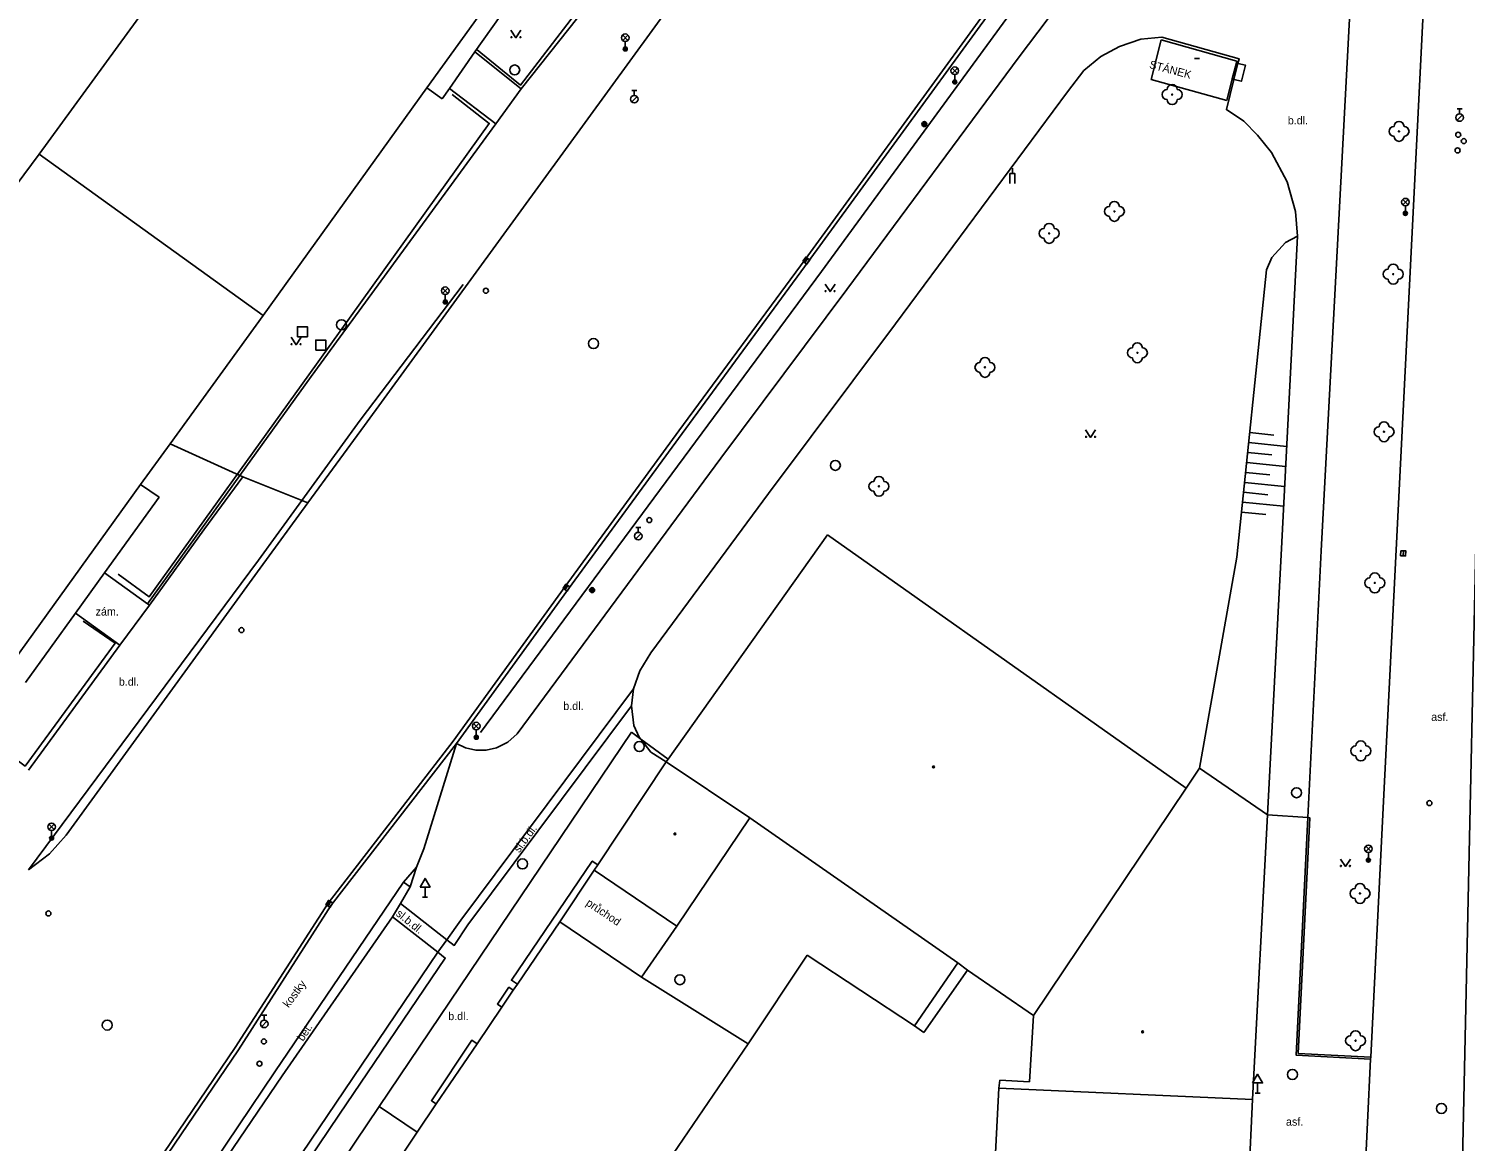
# Model space of a CAD drawing. Extents: x -599770 to -598493, y -1162076 to -1159209.
# Drawn here: x -599131.7 to -599059.8, y -1159691.3 to -1159635.7 of the extents above; entities that cross this region are included whole.
import ezdxf

# ---------------------------------------------------------------- set-up
doc = ezdxf.new("R2010")
doc.units = 0
doc.layers.add('Podklad', color=7, linetype='Continuous')

msp = doc.modelspace()

# ---------------------------------------------------------------- linework, layer by layer
at = {"layer": 'Podklad'}
for p, q in [((-599101.962, -1159636.26), (-599101.697, -1159635.995)), ((-599101.962, -1159635.995), (-599101.697, -1159636.26)), ((-599101.83, -1159636.315), (-599101.83, -1159636.69)), ((-599073.37, -1159637.16), (-599073.12, -1159637.16)), ((-599085.492, -1159637.91), (-599085.227, -1159637.645)), ((-599085.492, -1159637.645), (-599085.227, -1159637.91)), ((-599085.36, -1159637.965), (-599085.36, -1159638.34)), ((-599101.509, -1159639.336), (-599101.244, -1159639.071)), ((-599101.505, -1159638.762), (-599101.255, -1159638.762)), ((-599101.38, -1159639.012), (-599101.38, -1159638.762)), ((-599060.249, -1159640.256), (-599059.984, -1159639.991)), ((-599060.245, -1159639.683), (-599059.995, -1159639.683)), ((-599060.12, -1159639.933), (-599060.12, -1159639.683)), ((-599082.48, -1159642.92), (-599082.48, -1159642.655)), ((-599062.962, -1159644.48), (-599062.697, -1159644.215)), ((-599062.962, -1159644.215), (-599062.697, -1159644.48)), ((-599062.83, -1159644.535), (-599062.83, -1159644.91)), ((-599092.853, -1159647.372), (-599092.707, -1159647.168)), ((-599110.962, -1159648.91), (-599110.697, -1159648.645)), ((-599110.962, -1159648.645), (-599110.697, -1159648.91)), ((-599110.83, -1159648.965), (-599110.83, -1159649.34)), ((-599101.305, -1159660.613), (-599101.055, -1159660.613)), ((-599101.18, -1159660.863), (-599101.18, -1159660.613)), ((-599101.309, -1159661.186), (-599101.044, -1159660.921)), ((-599062.933, -1159661.785), (-599062.947, -1159662.035)), ((-599104.841, -1159663.723), (-599104.699, -1159663.517)), ((-599109.413, -1159670.68), (-599109.148, -1159670.415)), ((-599109.413, -1159670.415), (-599109.148, -1159670.68)), ((-599109.28, -1159670.735), (-599109.28, -1159671.11)), ((-599130.643, -1159675.72), (-599130.378, -1159675.455)), ((-599130.643, -1159675.455), (-599130.378, -1159675.72)), ((-599130.51, -1159675.775), (-599130.51, -1159676.15)), ((-599064.812, -1159676.82), (-599064.547, -1159676.555)), ((-599064.812, -1159676.555), (-599064.547, -1159676.82)), ((-599064.68, -1159676.875), (-599064.68, -1159677.25)), ((-599111.84, -1159678.601), (-599111.84, -1159679.11)), ((-599116.692, -1159679.548), (-599116.568, -1159679.332)), ((-599111.965, -1159679.11), (-599111.715, -1159679.11)), ((-599120.005, -1159685.003), (-599119.755, -1159685.003)), ((-599119.88, -1159685.253), (-599119.88, -1159685.003)), ((-599120.009, -1159685.576), (-599119.744, -1159685.311)), ((-599070.22, -1159688.391), (-599070.22, -1159688.9)), ((-599070.345, -1159688.9), (-599070.095, -1159688.9))]:
    msp.add_line(p, q, dxfattribs=at)
for points in [[(-599081.54, -1159609.68), (-599084.49, -1159613.78), (-599087.085, -1159617.344), (-599114.87, -1159655.51)], [(-599070, -1159616.2), (-599070.21, -1159616.14), (-599079.64, -1159629.06), (-599092.84, -1159647.22), (-599099.15, -1159655.79), (-599104.83, -1159663.57), (-599110.43, -1159671.3), (-599116.69, -1159679.4), (-599121.33, -1159686.62), (-599127.73, -1159696.07), (-599130.7, -1159701.68), (-599133.59, -1159706.51), (-599136.75, -1159712.55), (-599137.64, -1159714.18), (-599138.29, -1159715.58), (-599145.74, -1159730.68), (-599147.39, -1159734.16)], [(-599104.67, -1159663.69), (-599098.99, -1159655.91), (-599092.68, -1159647.34), (-599079.48, -1159629.18), (-599070, -1159616.2)], [(-599109.07, -1159670.87), (-599092.02, -1159647.81), (-599078.8, -1159629.73), (-599071.94, -1159620.17), (-599070.03, -1159618.39), (-599068.94, -1159616.98)], [(-599068.94, -1159616.98), (-599068.84, -1159617.12), (-599068.63, -1159617.54), (-599068.53, -1159617.94), (-599068.5, -1159618.27), (-599068.57, -1159618.74), (-599077.37, -1159630.76), (-599082.14, -1159637.08), (-599090.75, -1159648.72)], [(-599061.78, -1159618.02), (-599062.25, -1159618.13), (-599062.76, -1159618.36), (-599063.23, -1159618.64), (-599063.66, -1159618.96), (-599064.04, -1159619.33), (-599064.4, -1159619.8), (-599064.68, -1159620.26), (-599064.86, -1159620.72), (-599066.21, -1159646.17), (-599067.04, -1159661.78), (-599067.71, -1159675.12)], [(-599061.09, -1159617.92), (-599062.51, -1159646.18), (-599063.97, -1159675.3), (-599064.56, -1159687.1)], [(-599131.14, -1159641.95), (-599118.52, -1159624.64)], [(-599064.99, -1159695.953), (-599060.021, -1159694.564), (-599058.503, -1159624.689)], [(-599107.41, -1159632.6), (-599111.75, -1159638.64), (-599119.94, -1159650.02)], [(-599109.36, -1159636.83), (-599106.73, -1159633.13)], [(-599104.37, -1159634.98), (-599107.07, -1159638.5), (-599109.24, -1159636.73)], [(-599107.03, -1159638.69), (-599104.2, -1159635.11)], [(-599107.55, -1159635.755), (-599107.3, -1159636.13), (-599107.05, -1159635.755)], [(-599079.73, -1159638.83), (-599078.91, -1159637.77), (-599078.06, -1159637.06), (-599077.12, -1159636.56), (-599076.05, -1159636.2), (-599075, -1159636.1), (-599071.14, -1159637.18), (-599071.2, -1159637.41)], [(-599075.54, -1159638.21), (-599075.04, -1159636.24)], [(-599075.04, -1159636.24), (-599071.26, -1159637.3)], [(-599110.98, -1159639.19), (-599110.62, -1159638.67), (-599109.36, -1159636.83)], [(-599107.03, -1159638.69), (-599109.36, -1159636.83)], [(-599071.28, -1159637.38), (-599071.49, -1159638.19)], [(-599071.2, -1159637.41), (-599070.82, -1159637.5), (-599071.03, -1159638.3), (-599071.4, -1159638.21)], [(-599071.4, -1159638.21), (-599071.2, -1159637.41)], [(-599071.26, -1159637.3), (-599071.28, -1159637.38)], [(-599071.2, -1159637.41), (-599071.28, -1159637.38)], [(-599071.76, -1159639.27), (-599075.54, -1159638.21)], [(-599071.4, -1159638.21), (-599071.78, -1159639.72), (-599070.9, -1159640.3), (-599070.22, -1159641), (-599069.52, -1159641.87), (-599068.74, -1159643.33), (-599068.32, -1159644.81), (-599068.22, -1159646.05)], [(-599071.49, -1159638.19), (-599071.76, -1159639.27)], [(-599071.4, -1159638.21), (-599071.49, -1159638.19)], [(-599110.48, -1159638.97), (-599108.63, -1159640.41), (-599117.65, -1159652.99), (-599125.63, -1159664.08), (-599127.19, -1159662.96)], [(-599110.98, -1159639.19), (-599111.75, -1159638.64)], [(-599110.62, -1159638.67), (-599108.3, -1159640.43)], [(-599108.3, -1159640.43), (-599107.03, -1159638.69)], [(-599100.55, -1159666.88), (-599094.67, -1159658.92), (-599088.33, -1159650.43), (-599079.73, -1159638.83)], [(-599121.1, -1159658.02), (-599117.53, -1159653.07), (-599108.3, -1159640.43)], [(-599139.39, -1159653.05), (-599131.14, -1159641.95)], [(-599119.94, -1159650.02), (-599131.14, -1159641.95)], [(-599082.605, -1159643.42), (-599082.605, -1159642.92), (-599082.355, -1159642.92), (-599082.355, -1159643.42)], [(-599073.12, -1159672.65), (-599071.25, -1159662.1), (-599069.77, -1159647.73), (-599069.51, -1159647.12), (-599068.83, -1159646.37), (-599068.22, -1159646.05)], [(-599068.22, -1159646.05), (-599069.03, -1159661.67), (-599069.72, -1159674.98)], [(-599109.93, -1159648.46), (-599115.08, -1159655.25), (-599120.16, -1159662.25), (-599131.66, -1159677.74)], [(-599091.84, -1159648.445), (-599091.59, -1159648.82), (-599091.34, -1159648.445)], [(-599090.75, -1159648.72), (-599097.06, -1159657.15), (-599107.24, -1159670.93), (-599107.7, -1159671.35), (-599108.27, -1159671.64), (-599108.78, -1159671.75), (-599109.3, -1159671.76), (-599109.82, -1159671.63), (-599110.27, -1159671.42)], [(-599119.94, -1159650.02), (-599124.59, -1159656.44), (-599126.06, -1159658.47)], [(-599118.54, -1159651.105), (-599118.29, -1159651.48), (-599118.04, -1159651.105)], [(-599114.87, -1159655.51), (-599117.7, -1159659.38), (-599120.09, -1159662.66), (-599129.78, -1159676)], [(-599078.82, -1159655.735), (-599078.57, -1159656.11), (-599078.32, -1159655.735)], [(-599120.949, -1159658.09), (-599120.986, -1159658.076), (-599121.1, -1159658.02), (-599124.59, -1159656.44)], [(-599068.77, -1159656.57), (-599070.66, -1159656.37)], [(-599069.4, -1159656), (-599070.61, -1159655.87)], [(-599069.51, -1159656.99), (-599070.71, -1159656.87)], [(-599069.61, -1159657.98), (-599070.81, -1159657.86)], [(-599068.82, -1159657.57), (-599070.76, -1159657.36)], [(-599126.06, -1159658.47), (-599132.74, -1159667.73)], [(-599126.06, -1159658.47), (-599125.14, -1159659.11)], [(-599125.72, -1159664.43), (-599121.1, -1159658.02)], [(-599125.62, -1159664.5), (-599122.9, -1159660.73), (-599120.95, -1159658.09)], [(-599117.7, -1159659.38), (-599120.949, -1159658.09)], [(-599068.87, -1159658.56), (-599070.86, -1159658.36)], [(-599125.14, -1159659.11), (-599127.86, -1159662.88)], [(-599068.92, -1159659.56), (-599070.97, -1159659.35)], [(-599069.71, -1159658.98), (-599070.92, -1159658.86)], [(-599069.81, -1159659.97), (-599071.02, -1159659.85)], [(-599099.68, -1159672.2), (-599091.72, -1159660.98)], [(-599091.72, -1159660.98), (-599073.79, -1159673.65)], [(-599127.86, -1159662.88), (-599129.32, -1159664.9)], [(-599127.86, -1159662.88), (-599125.72, -1159664.43), (-599125.62, -1159664.5)], [(-599110.27, -1159671.42), (-599104.67, -1159663.69)], [(-599129.32, -1159664.9), (-599131.82, -1159668.37)], [(-599127.1, -1159666.5), (-599129.32, -1159664.9)], [(-599127.1, -1159666.5), (-599125.62, -1159664.5)], [(-599133.79, -1159671.11), (-599131.84, -1159672.55), (-599127.34, -1159666.41), (-599128.93, -1159665.3)], [(-599131.66, -1159672.76), (-599127.1, -1159666.5)], [(-599101.42, -1159668.69), (-599101.11, -1159667.78), (-599100.55, -1159666.88)], [(-599101.42, -1159668.69), (-599110.06, -1159680.25), (-599110.75, -1159681.23)], [(-599101.52, -1159669.53), (-599101.42, -1159668.69)], [(-599110.75, -1159681.23), (-599110.38, -1159681.52), (-599109.71, -1159680.49), (-599101.52, -1159669.53)], [(-599101.05, -1159671.2), (-599101.13, -1159671.1), (-599101.4, -1159670.52), (-599101.52, -1159669.53)], [(-599101.52, -1159670.86), (-599114.13, -1159689.57)], [(-599101.05, -1159671.2), (-599101.52, -1159670.86)], [(-599110.27, -1159671.42), (-599116.53, -1159679.51), (-599121.16, -1159686.73), (-599127.56, -1159696.17), (-599130.53, -1159701.78)], [(-599112.27, -1159677.6), (-599112.07, -1159677.11), (-599111.91, -1159676.69), (-599110.27, -1159671.42)], [(-599099.78, -1159672.34), (-599100.55, -1159671.86), (-599101.05, -1159671.2)], [(-599099.68, -1159672.2), (-599101.05, -1159671.2)], [(-599103.21, -1159677.49), (-599099.78, -1159672.34)], [(-599099.78, -1159672.34), (-599099.68, -1159672.2)], [(-599095.61, -1159675.14), (-599099.78, -1159672.34)], [(-599073.79, -1159673.65), (-599073.12, -1159672.65)], [(-599073.12, -1159672.65), (-599069.72, -1159674.98)], [(-599073.79, -1159673.65), (-599081.43, -1159685.02)], [(-599095.61, -1159675.14), (-599099.25, -1159680.56)], [(-599085.21, -1159682.39), (-599095.61, -1159675.14)], [(-599069.72, -1159674.98), (-599070.47, -1159689.22)], [(-599067.71, -1159675.12), (-599069.72, -1159674.98)], [(-599067.71, -1159675.12), (-599068.29, -1159687.01), (-599064.57, -1159687.2)], [(-599067.71, -1159675.12), (-599067.61, -1159675.13), (-599068.19, -1159686.92), (-599064.56, -1159687.1)], [(-599129.78, -1159676), (-599130.61, -1159676.93), (-599131.66, -1159677.74)], [(-599107.22, -1159683.46), (-599107.52, -1159683.26), (-599103.48, -1159677.3), (-599103.21, -1159677.49)], [(-599066.08, -1159677.195), (-599065.83, -1159677.57), (-599065.58, -1159677.195)], [(-599112.92, -1159678.36), (-599112.27, -1159677.6)], [(-599112.59, -1159678.59), (-599112.27, -1159677.6)], [(-599105.1, -1159680.33), (-599103.39, -1159677.76)], [(-599103.39, -1159677.76), (-599103.21, -1159677.49)], [(-599099.25, -1159680.56), (-599103.39, -1159677.76)], [(-599112.92, -1159678.36), (-599119.35, -1159687.83), (-599124.8, -1159695.93)], [(-599113.07, -1159679.42), (-599112.59, -1159678.59)], [(-599112.59, -1159678.59), (-599112.92, -1159678.36)], [(-599113.47, -1159680.09), (-599113.07, -1159679.42)], [(-599113.07, -1159679.42), (-599110.75, -1159681.23)], [(-599124.49, -1159696.14), (-599118.98, -1159688.03), (-599113.47, -1159680.09)], [(-599113.47, -1159680.09), (-599111.2, -1159681.86)], [(-599107.22, -1159683.46), (-599105.1, -1159680.33)], [(-599105.1, -1159680.33), (-599101.02, -1159683.1)], [(-599099.25, -1159680.56), (-599101.02, -1159683.1)], [(-599110.75, -1159681.23), (-599111.2, -1159681.86)], [(-599111.2, -1159681.86), (-599121.81, -1159697.57), (-599126.73, -1159704.94), (-599128.45, -1159707.76), (-599130.07, -1159710.85), (-599131.65, -1159713.97)], [(-599111.2, -1159681.86), (-599110.83, -1159682.15), (-599116.12, -1159689.95), (-599121.42, -1159697.83), (-599122.55, -1159699.48)], [(-599095.69, -1159686.44), (-599092.73, -1159682.01)], [(-599092.73, -1159682.01), (-599087.37, -1159685.53)], [(-599085.21, -1159682.39), (-599087.37, -1159685.53)], [(-599084.73, -1159682.75), (-599085.21, -1159682.39)], [(-599101.02, -1159683.1), (-599095.69, -1159686.44)], [(-599086.9, -1159685.87), (-599084.73, -1159682.75)], [(-599081.43, -1159685.02), (-599084.73, -1159682.75)], [(-599108, -1159684.6), (-599108.22, -1159684.45), (-599107.65, -1159683.61), (-599107.43, -1159683.76)], [(-599108, -1159684.6), (-599107.43, -1159683.76)], [(-599107.43, -1159683.76), (-599107.22, -1159683.46)], [(-599109.24, -1159686.43), (-599108, -1159684.6)], [(-599081.63, -1159688.33), (-599081.43, -1159685.02)], [(-599087.37, -1159685.53), (-599086.9, -1159685.87)], [(-599111.28, -1159689.44), (-599111.52, -1159689.28), (-599109.5, -1159686.25), (-599109.24, -1159686.43)], [(-599111.28, -1159689.44), (-599109.24, -1159686.43)], [(-599095.69, -1159686.44), (-599099.69, -1159692.3)], [(-599064.57, -1159687.2), (-599064.88, -1159693.54)], [(-599064.56, -1159687.1), (-599064.57, -1159687.2)], [(-599083.35, -1159692.54), (-599083.16, -1159688.66)], [(-599083.16, -1159688.66), (-599083.1, -1159688.25)], [(-599070.47, -1159689.22), (-599083.16, -1159688.66)], [(-599083.1, -1159688.25), (-599081.63, -1159688.33)], [(-599114.13, -1159689.57), (-599121.33, -1159700.27)], [(-599112.24, -1159690.86), (-599114.13, -1159689.57)], [(-599112.24, -1159690.86), (-599111.28, -1159689.44)], [(-599070.47, -1159689.22), (-599070.65, -1159693.16)], [(-599117.36, -1159698.54), (-599112.24, -1159690.86)]]:
    msp.add_lwpolyline(points, dxfattribs=at)
for points in [[(-599092.751, -1159647.444), (-599092.606, -1159647.241), (-599092.809, -1159647.096), (-599092.954, -1159647.299)], [(-599118.22, -1159651.08), (-599117.72, -1159651.08), (-599117.72, -1159650.58), (-599118.22, -1159650.58)], [(-599117.31, -1159651.75), (-599116.81, -1159651.75), (-599116.81, -1159651.25), (-599117.31, -1159651.25)], [(-599063.058, -1159661.778), (-599063.072, -1159662.028), (-599062.822, -1159662.042), (-599062.808, -1159661.792)], [(-599104.739, -1159663.794), (-599104.596, -1159663.589), (-599104.801, -1159663.446), (-599104.944, -1159663.651)], [(-599112.09, -1159678.601), (-599111.59, -1159678.601), (-599111.84, -1159678.168)], [(-599116.584, -1159679.611), (-599116.459, -1159679.394), (-599116.676, -1159679.269), (-599116.801, -1159679.486)], [(-599070.47, -1159688.391), (-599069.97, -1159688.391), (-599070.22, -1159687.958)]]:
    msp.add_lwpolyline(points, close=True, dxfattribs=at)
for centre, radius in [((-599107.525, -1159636.105), 0.025), ((-599107.075, -1159636.105), 0.025), ((-599101.83, -1159636.128), 0.188), ((-599101.83, -1159636.69), 0.1), ((-599101.83, -1159636.69), 0.0723), ((-599101.83, -1159636.69), 0.0438), ((-599107.36, -1159637.74), 0.25), ((-599085.36, -1159637.777), 0.188), ((-599085.36, -1159638.34), 0.1), ((-599085.36, -1159638.34), 0.0723), ((-599085.36, -1159638.34), 0.0438), ((-599101.38, -1159639.2), 0.188), ((-599074.49, -1159638.97), 0.025), ((-599060.12, -1159640.12), 0.188), ((-599086.88, -1159640.45), 0.125), ((-599086.88, -1159640.45), 0.1), ((-599086.88, -1159640.45), 0.075), ((-599086.88, -1159640.45), 0.05), ((-599086.88, -1159640.45), 0.025), ((-599063.15, -1159640.81), 0.025), ((-599060.19, -1159640.98), 0.125), ((-599059.91, -1159641.3), 0.125), ((-599060.22, -1159641.76), 0.125), ((-599062.83, -1159644.347), 0.188), ((-599077.38, -1159644.81), 0.025), ((-599062.83, -1159644.91), 0.1), ((-599062.83, -1159644.91), 0.0723), ((-599062.83, -1159644.91), 0.0438), ((-599080.64, -1159645.91), 0.025), ((-599063.44, -1159647.95), 0.025), ((-599110.83, -1159648.777), 0.188), ((-599108.8, -1159648.78), 0.125), ((-599110.83, -1159649.34), 0.1), ((-599110.83, -1159649.34), 0.0723), ((-599110.83, -1159649.34), 0.0438), ((-599091.815, -1159648.795), 0.025), ((-599091.365, -1159648.795), 0.025), ((-599116.02, -1159650.48), 0.25), ((-599118.515, -1159651.455), 0.025), ((-599118.065, -1159651.455), 0.025), ((-599103.42, -1159651.42), 0.25), ((-599076.23, -1159651.88), 0.025), ((-599083.85, -1159652.61), 0.025), ((-599063.9, -1159655.83), 0.025), ((-599078.795, -1159656.085), 0.025), ((-599078.345, -1159656.085), 0.025), ((-599091.33, -1159657.51), 0.25), ((-599089.15, -1159658.56), 0.025), ((-599100.63, -1159660.25), 0.125), ((-599101.18, -1159661.05), 0.188), ((-599103.49, -1159663.75), 0.125), ((-599103.49, -1159663.75), 0.1), ((-599103.49, -1159663.75), 0.075), ((-599103.49, -1159663.75), 0.05), ((-599103.49, -1159663.75), 0.025), ((-599064.36, -1159663.39), 0.025), ((-599121.02, -1159665.75), 0.125), ((-599109.28, -1159670.547), 0.188), ((-599109.28, -1159671.11), 0.1), ((-599109.28, -1159671.11), 0.0723), ((-599109.28, -1159671.11), 0.0438), ((-599101.13, -1159671.57), 0.25), ((-599065.06, -1159671.79), 0.025), ((-599086.42, -1159672.59), 0.045), ((-599086.42, -1159672.59), 0.0199), ((-599068.27, -1159673.88), 0.25), ((-599061.63, -1159674.4), 0.125), ((-599130.51, -1159675.587), 0.188), ((-599099.35, -1159675.94), 0.045), ((-599099.35, -1159675.94), 0.0199), ((-599130.51, -1159676.15), 0.1), ((-599130.51, -1159676.15), 0.0723), ((-599130.51, -1159676.15), 0.0438), ((-599064.68, -1159676.688), 0.188), ((-599106.97, -1159677.44), 0.25), ((-599064.68, -1159677.25), 0.1), ((-599064.68, -1159677.25), 0.0723), ((-599064.68, -1159677.25), 0.0438), ((-599066.055, -1159677.545), 0.025), ((-599065.605, -1159677.545), 0.025), ((-599065.1, -1159678.92), 0.025), ((-599130.67, -1159679.92), 0.125), ((-599099.1, -1159683.23), 0.25), ((-599127.73, -1159685.5), 0.25), ((-599119.88, -1159685.44), 0.188), ((-599075.97, -1159685.84), 0.045), ((-599075.97, -1159685.84), 0.0199), ((-599119.9, -1159686.32), 0.125), ((-599065.32, -1159686.28), 0.025), ((-599120.12, -1159687.43), 0.125), ((-599068.48, -1159687.97), 0.25), ((-599061.03, -1159689.67), 0.25)]:
    msp.add_circle(centre, radius, dxfattribs=at)
for centre, start, end in [((-599074.49, -1159638.72), 0, 180), ((-599074.74, -1159638.97), 90, 270), ((-599074.49, -1159639.22), 180, 0), ((-599074.24, -1159638.97), 270, 90), ((-599063.4, -1159640.81), 90, 270), ((-599063.15, -1159640.56), 0, 180), ((-599062.9, -1159640.81), 270, 90), ((-599063.15, -1159641.06), 180, 0), ((-599077.38, -1159644.56), 0, 180), ((-599077.63, -1159644.81), 90, 270), ((-599077.38, -1159645.06), 180, 0), ((-599077.13, -1159644.81), 270, 90), ((-599080.89, -1159645.91), 90, 270), ((-599080.64, -1159645.66), 0, 180), ((-599080.39, -1159645.91), 270, 90), ((-599080.64, -1159646.16), 180, 0), ((-599063.69, -1159647.95), 90, 270), ((-599063.44, -1159647.7), 0, 180), ((-599063.19, -1159647.95), 270, 90), ((-599063.44, -1159648.2), 180, 0), ((-599076.23, -1159651.63), 0, 180), ((-599083.85, -1159652.36), 0, 180), ((-599076.48, -1159651.88), 90, 270), ((-599076.23, -1159652.13), 180, 0), ((-599075.98, -1159651.88), 270, 90), ((-599084.1, -1159652.61), 90, 270), ((-599083.85, -1159652.86), 180, 0), ((-599083.6, -1159652.61), 270, 90), ((-599064.15, -1159655.83), 90, 270), ((-599063.9, -1159655.58), 0, 180), ((-599063.65, -1159655.83), 270, 90), ((-599063.9, -1159656.08), 180, 0), ((-599089.4, -1159658.56), 90, 270), ((-599089.15, -1159658.31), 0, 180), ((-599088.9, -1159658.56), 270, 90), ((-599089.15, -1159658.81), 180, 0), ((-599064.36, -1159663.14), 0, 180), ((-599064.61, -1159663.39), 90, 270), ((-599064.36, -1159663.64), 180, 0), ((-599064.11, -1159663.39), 270, 90), ((-599065.31, -1159671.79), 90, 270), ((-599065.06, -1159671.54), 0, 180), ((-599064.81, -1159671.79), 270, 90), ((-599065.06, -1159672.04), 180, 0), ((-599065.35, -1159678.92), 90, 270), ((-599065.1, -1159678.67), 0, 180), ((-599064.85, -1159678.92), 270, 90), ((-599065.1, -1159679.17), 180, 0), ((-599065.32, -1159686.03), 0, 180), ((-599065.57, -1159686.28), 90, 270), ((-599065.32, -1159686.53), 180, 0), ((-599065.07, -1159686.28), 270, 90)]:
    msp.add_arc(centre, 0.25, start, end, dxfattribs=at)

# ---------------------------------------------------------------- texts
for s, rotation, p in [('STÁNEK', 345.22, (-599075.66, -1159637.64)), ('sl.b.dl.', 53.85, (-599107.13, -1159676.91)), ('průchod', 326.21, (-599103.83, -1159679.48)), ('sl.b.dl.', 321.01, (-599113.33, -1159679.99)), ('kostky', 53.6, (-599118.66, -1159684.66)), ('bet.', 56.63, (-599117.94, -1159686.34))]:
    msp.add_text(s, height=0.4, rotation=rotation, dxfattribs=at).set_placement(p)
for s, p in [('b.dl.', (-599068.71, -1159640.46)), ('zám.', (-599128.31, -1159665.02)), ('b.dl.', (-599127.15, -1159668.53)), ('b.dl.', (-599104.93, -1159669.74)), ('asf.', (-599061.54, -1159670.29)), ('b.dl.', (-599110.68, -1159685.25)), ('asf.', (-599068.8, -1159690.53))]:
    msp.add_text(s, height=0.4, dxfattribs=at).set_placement(p)

doc.saveas('drawing.dxf')
